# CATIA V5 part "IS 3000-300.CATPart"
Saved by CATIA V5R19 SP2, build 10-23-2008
Part number: IS 3000-300
Bounding box of the stored display mesh (mm): x -47.487 to 47.487, y -47.487 to 47.487, z 0 to 720
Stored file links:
  C:\Users\Bora\Desktop\3D Katı model\IS serisi\IS 3000\IS 3000-300.CATPart
  C:\Program Files\Dassault Systemes\B19\intel_a\reffiles\standard\MetricThickPitch.txt
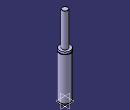
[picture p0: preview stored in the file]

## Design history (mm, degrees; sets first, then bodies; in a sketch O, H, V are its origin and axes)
Body1 (main body)
  Sketch1 on yz-plane, origin (0, 0, 0), H (0, 1, 0), V (0, 0, 1)
    point P1 (47.5, 398.5)
    point P2 (47.5, 393.5)
    point P5 (25, 719)
    point P7 (25, 719)
    point P12 (47.5, 393.5)
    point P13 (47.5, 398.5)
    arc A1 centre (47.5, 396) radius 2.5 from (47.5, 398.5) to (47.5, 393.5) ccw
    line L1 (47.5, 0) -> (47.5, 8)
    line L2 (25, 719) -> (25, 417)
    arc A2 centre (24, 719) radius 1 from (25, 719) to (24, 720) ccw
    line L3 (43.5, 13) -> (43.5, 8)
    line L4 (47.5, 13) -> (47.5, 393.5)
    line L5 (47.5, 398.5) -> (47.5, 417)
    line L6 (24, 720) -> (0, 720)
    point P15 (0, 720)
    line L7 (25, 417) -> (47.5, 417)
    line L8 (0, 0) -> (47.5, 0)
    line L9 (43.5, 8) -> (47.5, 8)
    line L10 (43.5, 13) -> (47.5, 13)
    coincidence: P15 V, P1 P13, P2 P12, P5 P7
    tangency: L6 A2
    horizontal: L7 H, L8 H, L9 H, L10 H
  Shaft1: profile Sketch1, axis Sketch1.V, angle 360
  Sketch2 on face of Shaft1 from Sketch1.L8, origin (0, 0, 0), H (1, 0, 0), V (0, -1, 0)
    point P1 (30, 0)
    distance P1 V = 30
  Hole1: placed by Sketch2, at (30, 0, 0) direction (0, 0, 1), diameter 6.647, depth 13, threaded "M8", thread diameter 8, thread depth 13, pitch 1.25
  CircPattern1: of Hole1, instances 4, angular step 90, axis from xy-plane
